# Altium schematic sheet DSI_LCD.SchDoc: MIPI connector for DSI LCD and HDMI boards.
size A4; Date: 29-OCT-2015; Author: A.B; CompanyName: STMicroelectronics; Organization: MCD/TOOLS/GNB; Address1: 12, Rue Jules HOROWITZ; Address2: 38019 Grenoble; Address3: FRANCE; DocumentNumber: MB1225; Revision: B-01; SheetNumber: 12; SheetTotal: 13; Project: STM32F769I-DISCO
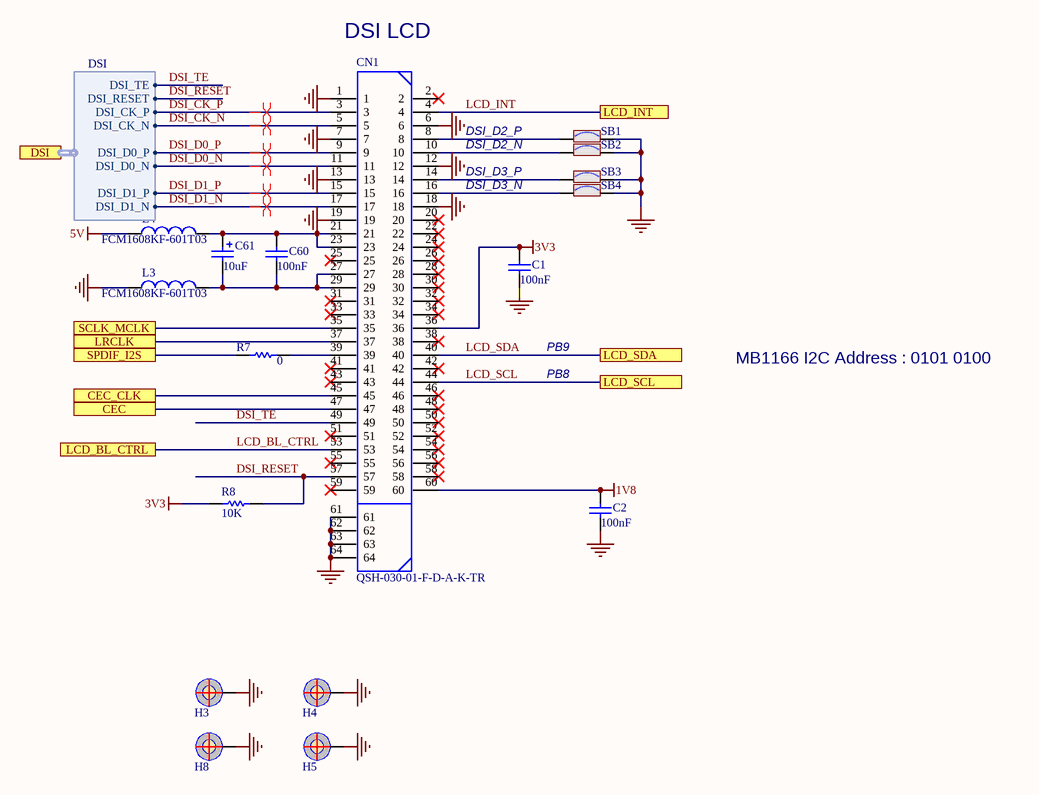
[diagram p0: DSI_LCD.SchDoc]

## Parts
C1  100nF  [0603C]
C2  100nF  [0603C]
C60  100nF  [0603C]
C61  10uF  [TAN-A]
CN1  QSH-030-01-F-D-A-K-TR  [QSH-030-01-F-D-A]
H3  POSITION HOLE  [HOLE_C9D4R5-1]  (value not drawn)
H4  POSITION HOLE  [HOLE_C9D4R5]  (value not drawn)
H5  POSITION HOLE  [HOLE_C9D4R5]  (value not drawn)
H8  POSITION HOLE  [HOLE_C9D4R5-1]  (value not drawn)
L3  FCM1608KF-601T03  [0603L]
L4  FCM1608KF-601T03  [0603L]
R7  0  [0402R]
R8  10K  [0402R]
SB1  Solder Bridge ON  [JP2_SMD]  (value not drawn)
SB2  Solder Bridge ON  [JP2_SMD]  (value not drawn)
SB3  Solder Bridge ON  [JP2_SMD]  (value not drawn)
SB4  Solder Bridge ON  [JP2_SMD]  (value not drawn)

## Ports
CEC, CEC_CLK, DSI (harness DSI), LCD_BL_CTRL, LCD_INT, LCD_SCL, LCD_SDA, LRCLK, SCLK_MCLK, SPDIF_I2S

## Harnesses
DSI: DSI_CK_P, DSI_CK_N, DSI_D0_P, DSI_D0_N, DSI_D1_P, DSI_D1_N, DSI_TE, DSI_RESET

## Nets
1V8: C2.2 CN1.60
3V3: C1.2 CN1.36 R8.1
5V: L4.1
GND: C1.1 C2.1 CN1.1 CN1.6 CN1.7 CN1.12 CN1.13 CN1.18 CN1.19 CN1.61 CN1.62 CN1.63 CN1.64 H3.1 H4.1 H5.1 H8.1 L3.1 SB1.2 SB2.2 SB3.2 SB4.2
CEC: CN1.47 ; port CEC
CEC_CLK: CN1.45 ; port CEC_CLK
DSI_CK_N: CN1.5 ; port DSI.DSI_CK_N
DSI_CK_P: CN1.3 ; port DSI.DSI_CK_P
DSI_D0_N: CN1.11 ; port DSI.DSI_D0_N
DSI_D0_P: CN1.9 ; port DSI.DSI_D0_P
DSI_D1_N: CN1.17 ; port DSI.DSI_D1_N
DSI_D1_P: CN1.15 ; port DSI.DSI_D1_P
DSI_RESET: CN1.57 R8.2 ; port DSI.DSI_RESET
DSI_TE: CN1.49 ; port DSI.DSI_TE
LCD_BL_CTRL: CN1.53 ; port LCD_BL_CTRL
LCD_INT: CN1.4 ; port LCD_INT
LCD_SCL: CN1.44 ; port LCD_SCL
LCD_SDA: CN1.40 ; port LCD_SDA
LRCLK: CN1.37 ; port LRCLK
SCLK_MCLK: CN1.35 ; port SCLK_MCLK
SPDIF_I2S: R7.1 ; port SPDIF_I2S
NetC60_1: C60.1 C61.2 CN1.27 CN1.29 L3.2
NetC60_2: C60.2 C61.1 CN1.21 CN1.23 L4.2
NetCN1_8: CN1.8 SB1.1
NetCN1_10: CN1.10 SB2.1
NetCN1_14: CN1.14 SB3.1
NetCN1_16: CN1.16 SB4.1
NetCN1_39: CN1.39 R7.2

Not connected (* = marked no-connect by the designer): CN1 2* 20* 22* 24* 25* 26* 28* 30* 31* 32* 33* 34* 38* 41* 42* 43* 46* 48* 50* 51* 52* 54* 55* 56* 58* 59*

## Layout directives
differential pair: DSI_CK_N, DSI_CK_P, DSI_D0_N, DSI_D0_P, DSI_D1_N, DSI_D1_P

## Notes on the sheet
- DSI LCD
- DSI_D2_P
- DSI_D2_N
- DSI_D3_P
- DSI_D3_N
- PB9
- PB8
- MB1166 I2C Address : 0101 0100

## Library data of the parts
C1 C2 C60 = Cap_100nF_X7R_10%_0603: Capacitor,100nF,16V,X7R,10%,0603,YAGEO; Manuf_Part_1: CC0603KRX7R9BB104
C61 = Cap_10uF_POL_10%_TANA: Polarized Capacitor,10uF,10V,10%,typeA,VISHAY; Manuf_Part_1: 293D106X9010A2TE3
CN1 = QSH-030-01-F-D-A: HIGH SPEED SOCKET STRIP, .5mm PITCH, 60 PINS; Manuf_1: SAMTEC; Provided: Sub Co; Ref St: 9183715
L3 L4 = BEAD_600R_350MA_0603: Bead,600R,350mA,0603,FCM1608KF-601T03,Tai-tech; Manuf_2: TDK; Manuf_Part_2: MPZ1608S300A; Manuf_Part_3: BLM18PG121SN1D; Manuf_3: MURATA; Value: 100uH; Description_2: Bead,30R,5A,0603,MPZ1608S300A,TDK; Description_3: Bead,120R,2A,0603,BLM18PG121SN1D,MURATA
R7 = Res_0_5%_0402: Resistor,0,0402,5%,YAGEO; Manuf_Part_1: RC0402JR-070RL; Order: 2363467
R8 = Res_10K_1%_0402: Resistor,10K,0402,1%,YAGEO; Manuf_Part_1: RC0402FR-0710KL
SB1-SB4 = SB_ON: Solder: YES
